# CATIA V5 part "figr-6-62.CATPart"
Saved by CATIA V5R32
Part number: Part1
Bounding box of the stored display mesh (mm): x -50.648 to 50.648, y -72.183 to 72.183, z -40 to 40
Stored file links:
  D:\PROJECTS\Project 2022\CATIA V5 6R 2022\Resources\Part Files\c06_catia_v5_6r2022_prt\figr-6-62.CATPart
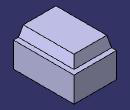
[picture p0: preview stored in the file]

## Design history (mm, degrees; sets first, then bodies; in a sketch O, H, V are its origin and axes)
Set1
  Plane1: type Offset, RefPlane xy-plane, Offset 20
Body1 (main body)
  Sketch1 on xy-plane, origin (0, 0, 0), H (1, 0, 0), V (0, 1, 0)
    line L1 (-50.6478, 72.1832) -> (50.6478, 72.1832)
    line L2 (50.6478, 72.1832) -> (50.6478, -72.1832)
    line L3 (50.6478, -72.1832) -> (-50.6478, -72.1832)
    line L4 (-50.6478, -72.1832) -> (-50.6478, 72.1832)
    axis line L5 (50.6478, -72.1832) -> (-50.6478, 72.1832)
    horizontal: L1 H, L3 H
    vertical: L2 V, L4 V
    midpoint: O L5
  Pad1: profile Sketch1, direction (0, 0, 1), length 40, mirrored extent
  Draft1: Angle 30, Neutral xy-plane, Parting Plane1, PullDir (0, 0, 1), SupportToDraft (face of Pad1; face of Pad1)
